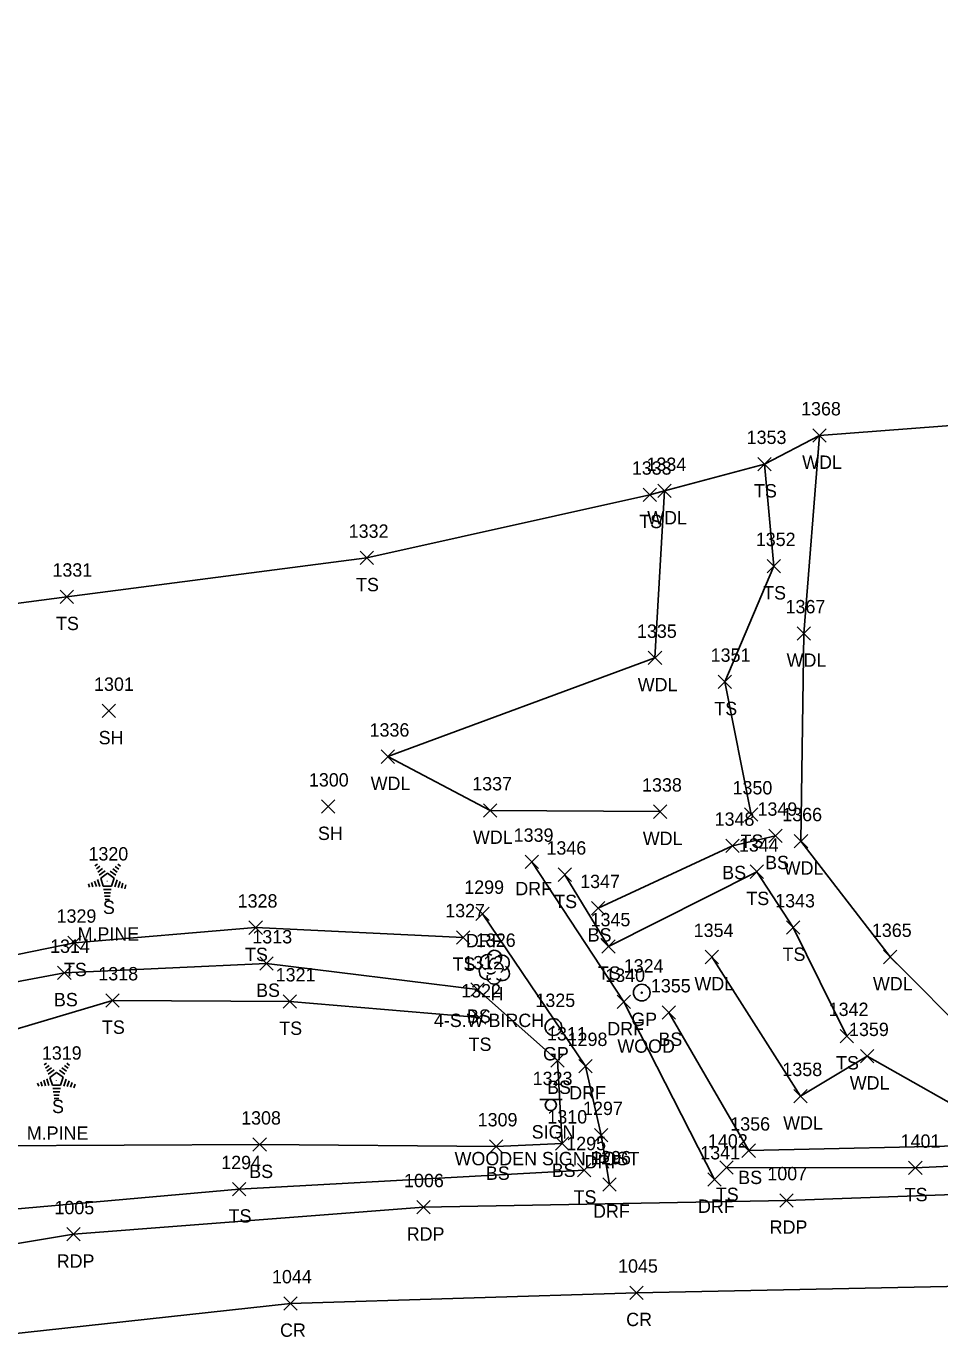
# Model space of a CAD drawing. Extents: x 1633660 to 1636532, y 388643 to 392631.
# Drawn here: x 1633769.3 to 1633906, y 388760.6 to 388957.6 of the extents above; entities that cross this region are included whole.
import ezdxf

# ---------------------------------------------------------------- set-up
doc = ezdxf.new("R2010")
doc.units = 0
for name, color, linetype in [('L_A', 7, 'Continuous'), ('L_C', 7, 'Continuous'), ('L_I', 7, 'Continuous'), ('L_TIC', 7, 'Continuous'), ('LAWA', 7, 'Continuous'), ('LELB', 7, 'Continuous'), ('LSOGP', 7, 'Continuous'), ('LTC', 7, 'Continuous'), ('LTD', 7, 'Continuous'), ('P_A', 7, 'Continuous'), ('P_I', 7, 'Continuous'), ('P_TIC', 7, 'Continuous'), ('PET', 7, 'Continuous'), ('PRC', 7, 'Continuous'), ('R_A', 7, 'Continuous'), ('R_C', 7, 'Continuous'), ('R_I', 7, 'Continuous'), ('R_TIC', 7, 'Continuous'), ('RDF', 7, 'Continuous'), ('RGP', 7, 'Continuous'), ('S_A', 7, 'Continuous'), ('S_C', 7, 'Continuous'), ('S_I', 7, 'Continuous'), ('SSGN', 7, 'Continuous')]:
    doc.layers.add(name, color=color, linetype=linetype)

msp = doc.modelspace()

# ---------------------------------------------------------------- linework, layer by layer
at = {"layer": 'L_TIC'}
for points in [[(1633886.99, 388895.34), (1633888.99, 388897.34)], [(1633888.99, 388895.34), (1633886.99, 388897.34)], [(1633878.79, 388891.06), (1633880.79, 388893.06)], [(1633880.79, 388891.06), (1633878.79, 388893.06)], [(1633861.62, 388886.47), (1633863.62, 388888.47)], [(1633863.62, 388886.47), (1633861.62, 388888.47)], [(1633863.8, 388887.03), (1633865.8, 388889.03)], [(1633865.8, 388887.03), (1633863.8, 388889.03)], [(1633819.24, 388877.02), (1633821.24, 388879.02)], [(1633821.24, 388877.02), (1633819.24, 388879.02)], [(1633880.16, 388875.79), (1633882.16, 388877.79)], [(1633882.16, 388875.79), (1633880.16, 388877.79)], [(1633774.34, 388871.21), (1633776.34, 388873.21)], [(1633776.34, 388871.21), (1633774.34, 388873.21)], [(1633884.66, 388865.72), (1633886.66, 388867.72)], [(1633886.66, 388865.72), (1633884.66, 388867.72)], [(1633862.38, 388862.05), (1633864.38, 388864.05)], [(1633864.38, 388862.05), (1633862.38, 388864.05)], [(1633872.85, 388858.47), (1633874.85, 388860.47)], [(1633874.85, 388858.47), (1633872.85, 388860.47)], [(1633780.65, 388854.12), (1633782.65, 388856.12)], [(1633782.65, 388854.12), (1633780.65, 388856.12)], [(1633822.41, 388847.27), (1633824.41, 388849.27)], [(1633824.41, 388847.27), (1633822.41, 388849.27)], [(1633813.45, 388839.8), (1633815.45, 388841.8)], [(1633815.45, 388839.8), (1633813.45, 388841.8)], [(1633837.72, 388839.22), (1633839.72, 388841.22)], [(1633839.72, 388839.22), (1633837.72, 388841.22)], [(1633863.15, 388839.04), (1633865.15, 388841.04)], [(1633865.15, 388839.04), (1633863.15, 388841.04)], [(1633876.77, 388838.62), (1633878.77, 388840.62)], [(1633878.77, 388838.62), (1633876.77, 388840.62)], [(1633880.42, 388835.43), (1633882.42, 388837.43)], [(1633882.42, 388835.43), (1633880.42, 388837.43)], [(1633874, 388833.93), (1633876, 388835.93)], [(1633876, 388833.93), (1633874, 388835.93)], [(1633884.23, 388834.61), (1633886.23, 388836.61)], [(1633886.23, 388834.61), (1633884.23, 388836.61)], [(1633848.89, 388829.61), (1633850.89, 388831.61)], [(1633850.89, 388829.61), (1633848.89, 388831.61)], [(1633877.64, 388830.06), (1633879.64, 388832.06)], [(1633879.64, 388830.06), (1633877.64, 388832.06)], [(1633853.87, 388824.6), (1633855.87, 388826.6)], [(1633855.87, 388824.6), (1633853.87, 388826.6)], [(1633802.62, 388821.68), (1633804.62, 388823.68)], [(1633804.62, 388821.68), (1633802.62, 388823.68)], [(1633883.07, 388821.71), (1633885.07, 388823.71)], [(1633885.07, 388821.71), (1633883.07, 388823.71)], [(1633775.53, 388819.42), (1633777.53, 388821.42)], [(1633777.53, 388819.42), (1633775.53, 388821.42)], [(1633833.68, 388820.23), (1633835.68, 388822.23)], [(1633835.68, 388820.23), (1633833.68, 388822.23)], [(1633855.43, 388818.88), (1633857.43, 388820.88)], [(1633857.43, 388818.88), (1633855.43, 388820.88)], [(1633870.87, 388817.29), (1633872.87, 388819.29)], [(1633872.87, 388817.29), (1633870.87, 388819.29)], [(1633897.58, 388817.29), (1633899.58, 388819.29)], [(1633899.58, 388817.29), (1633897.58, 388819.29)], [(1633804.25, 388816.32), (1633806.25, 388818.32)], [(1633806.25, 388816.32), (1633804.25, 388818.32)], [(1633773.99, 388814.91), (1633775.99, 388816.91)], [(1633775.99, 388814.91), (1633773.99, 388816.91)], [(1633835.81, 388812.44), (1633837.81, 388814.44)], [(1633837.81, 388812.44), (1633835.81, 388814.44)], [(1633781.21, 388810.79), (1633783.21, 388812.79)], [(1633783.21, 388810.79), (1633781.21, 388812.79)], [(1633807.74, 388810.63), (1633809.74, 388812.63)], [(1633809.74, 388810.63), (1633807.74, 388812.63)], [(1633836.08, 388808.23), (1633838.08, 388810.23)], [(1633838.08, 388808.23), (1633836.08, 388810.23)], [(1633864.46, 388808.99), (1633866.46, 388810.99)], [(1633866.46, 388808.99), (1633864.46, 388810.99)], [(1633891.07, 388805.46), (1633893.07, 388807.46)], [(1633893.07, 388805.46), (1633891.07, 388807.46)], [(1633847.79, 388801.8), (1633849.79, 388803.8)], [(1633849.79, 388801.8), (1633847.79, 388803.8)], [(1633894.12, 388802.46), (1633896.12, 388804.46)], [(1633896.12, 388802.46), (1633894.12, 388804.46)], [(1633884.15, 388796.47), (1633886.15, 388798.47)], [(1633886.15, 388796.47), (1633884.15, 388798.47)], [(1633803.22, 388789.21), (1633805.22, 388791.21)], [(1633805.22, 388789.21), (1633803.22, 388791.21)], [(1633838.63, 388788.94), (1633840.63, 388790.94)], [(1633840.63, 388788.94), (1633838.63, 388790.94)], [(1633848.49, 388789.37), (1633850.49, 388791.37)], [(1633850.49, 388789.37), (1633848.49, 388791.37)], [(1633876.4, 388788.31), (1633878.4, 388790.31)], [(1633878.4, 388788.31), (1633876.4, 388790.31)], [(1633873.08, 388785.77), (1633875.08, 388787.77)], [(1633875.08, 388785.77), (1633873.08, 388787.77)], [(1633901.34, 388785.74), (1633903.34, 388787.74)], [(1633903.34, 388785.74), (1633901.34, 388787.74)], [(1633851.79, 388785.38), (1633853.79, 388787.38)], [(1633853.79, 388785.38), (1633851.79, 388787.38)], [(1633800.16, 388782.54), (1633802.16, 388784.54)], [(1633802.16, 388782.54), (1633800.16, 388784.54)]]:
    msp.add_lwpolyline(points, dxfattribs=at)
at = {"layer": 'LAWA'}
for points in [[(1633871.87, 388818.29), (1633885.15, 388797.47), (1633895.12, 388803.46), (1633913.82, 388792.88), (1633930.93, 388800.92), (1633911.2, 388805.65), (1633898.58, 388818.29), (1633885.23, 388835.61), (1633885.66, 388866.72), (1633887.99, 388896.34)], [(1633864.8, 388888.03), (1633863.38, 388863.05), (1633823.41, 388848.27), (1633838.72, 388840.22), (1633864.15, 388840.04)]]:
    msp.add_lwpolyline(points, dxfattribs=at)
at = {"layer": 'LELB'}
for points in [[(1633877.77, 388839.62), (1633873.85, 388859.47), (1633881.16, 388876.79), (1633879.79, 388892.06)], [(1633775.34, 388872.21), (1633820.24, 388878.02), (1633862.62, 388887.47)], [(1633690.59, 388853.77), (1633701.55, 388823.73), (1633717.77, 388794.21), (1633733.79, 388778.78), (1633764.59, 388780.31), (1633801.16, 388783.54), (1633852.79, 388786.38)], [(1633865.46, 388809.99), (1633877.4, 388789.31), (1633913.51, 388790.13), (1633934.95, 388796.07), (1633973.78, 388798.8), (1634008.4, 388803.18), (1634057.79, 388813.56), (1634087.95, 388824.89), (1634134.34, 388843.13)], [(1634140.78, 388840.91), (1634131.75, 388832.34), (1634088.08, 388818.52), (1634045.58, 388805.1), (1633995.02, 388794.98), (1633949.56, 388789), (1633902.34, 388786.74), (1633874.08, 388786.77)], [(1633854.87, 388825.6), (1633875, 388834.93), (1633881.42, 388836.43)], [(1633892.07, 388806.46), (1633884.07, 388822.71), (1633878.64, 388831.06), (1633856.43, 388819.88), (1633849.89, 388830.61)], [(1633834.68, 388821.23), (1633803.62, 388822.68), (1633776.53, 388820.42), (1633736.77, 388812.27)], [(1633732.52, 388802.79), (1633737.38, 388786.25), (1633763.6, 388790.01), (1633804.22, 388790.21), (1633839.63, 388789.94), (1633849.49, 388790.37), (1633848.79, 388802.8), (1633836.81, 388813.44), (1633805.25, 388817.32), (1633774.99, 388815.91), (1633736.68, 388808.76)], [(1633736.45, 388802.86), (1633755.65, 388803.9), (1633782.21, 388811.79), (1633808.74, 388811.63), (1633837.08, 388809.23)]]:
    msp.add_lwpolyline(points, dxfattribs=at)
at = {"layer": 'LSOGP'}
msp.add_lwpolyline([(1633910.94, 388898.06), (1633887.99, 388896.34), (1633879.79, 388892.06), (1633864.8, 388888.03), (1633862.62, 388887.47), (1633820.24, 388878.02), (1633775.34, 388872.21), (1633743.09, 388867.97), (1633701.66, 388850.69), (1633690.59, 388853.77), (1633685.99, 388855.24), (1633676.03, 388842.96), (1633671.44, 388843.54), (1633662.45, 388842.61), (1633668.86, 388816.92), (1633674.86, 388781.37), (1633677.6, 388769.11), (1633680.44, 388762.93), (1633681.12, 388754.49)], dxfattribs=at)
at = {"layer": 'LTC'}
for p, q in [((1633779.57, 388831.94), (1633779.93, 388832.2)), ((1633779.78, 388831.48), (1633780.31, 388831.86)), ((1633779.99, 388831.01), (1633780.7, 388831.52)), ((1633780.2, 388830.54), (1633781.08, 388831.18)), ((1633781.86, 388831.14), (1633782.67, 388830.55)), ((1633782.23, 388831.48), (1633782.91, 388830.99)), ((1633782.6, 388831.83), (1633783.15, 388831.43)), ((1633782.97, 388832.18), (1633783.39, 388831.88)), ((1633778.61, 388829.22), (1633778.76, 388828.75)), ((1633779.06, 388829.44), (1633779.27, 388828.78)), ((1633779.52, 388829.65), (1633779.79, 388828.82)), ((1633779.97, 388829.87), (1633780.3, 388828.85)), ((1633780.43, 388830.09), (1633781.44, 388830.82)), ((1633780.43, 388830.09), (1633780.81, 388828.9)), ((1633781.44, 388830.82), (1633782.44, 388830.1)), ((1633782.44, 388830.1), (1633782.04, 388828.9)), ((1633782.87, 388829.83), (1633782.54, 388828.79)), ((1633783.32, 388829.58), (1633783.03, 388828.69)), ((1633783.76, 388829.33), (1633783.53, 388828.6)), ((1633784.21, 388829.08), (1633784.02, 388828.5)), ((1633782.04, 388828.9), (1633780.81, 388828.9)), ((1633782.01, 388828.4), (1633780.86, 388828.4)), ((1633781.92, 388827.9), (1633780.93, 388827.9)), ((1633781.84, 388827.4), (1633781.01, 388827.4)), ((1633781.76, 388826.9), (1633781.08, 388826.9)), ((1633771.96, 388802.14), (1633772.32, 388802.39)), ((1633772.17, 388801.67), (1633772.7, 388802.05)), ((1633772.38, 388801.2), (1633773.08, 388801.72)), ((1633772.59, 388800.74), (1633773.47, 388801.38)), ((1633774.62, 388801.68), (1633775.3, 388801.19)), ((1633774.99, 388802.03), (1633775.54, 388801.63)), ((1633775.36, 388802.38), (1633775.78, 388802.07)), ((1633770.99, 388799.41), (1633771.15, 388798.95)), ((1633771.45, 388799.63), (1633771.66, 388798.98)), ((1633771.91, 388799.85), (1633772.18, 388799.01)), ((1633772.36, 388800.06), (1633772.69, 388799.04)), ((1633772.82, 388800.28), (1633773.83, 388801.02)), ((1633772.82, 388800.28), (1633773.2, 388799.09)), ((1633773.83, 388801.02), (1633774.82, 388800.29)), ((1633774.25, 388801.33), (1633775.06, 388800.74)), ((1633774.82, 388800.29), (1633774.43, 388799.09)), ((1633775.26, 388800.02), (1633774.92, 388798.98)), ((1633775.71, 388799.77), (1633775.42, 388798.89)), ((1633776.15, 388799.52), (1633775.91, 388798.79)), ((1633774.43, 388799.09), (1633773.2, 388799.09)), ((1633774.39, 388798.59), (1633773.25, 388798.59)), ((1633774.31, 388798.09), (1633773.32, 388798.09)), ((1633774.23, 388797.59), (1633773.4, 388797.59)), ((1633776.59, 388799.27), (1633776.41, 388798.7)), ((1633774.14, 388797.09), (1633773.47, 388797.09))]:
    msp.add_line(p, q, dxfattribs=at)
at = {"layer": 'LTD'}
msp.add_line((1633839.32, 388816.81), (1633839.32, 388816.81), dxfattribs=at)
msp.add_line((1633839.32, 388816.81), (1633839.32, 388816.81), dxfattribs=at)
msp.add_arc((1633839.37, 388818.25), 1.05, 335.5272, 180.9563, dxfattribs=at)
for centre, major_axis, ratio, start_param, end_param in [((1633838.24, 388816.1), (0.58, -1.04), 0.959034, 3.141593, 6.283185), ((1633838.53, 388817.48), (1.21, -0.51), 0.895232, 1.570796, 4.712389), ((1633839.11, 388817.27), (-0.208, -0.792), 0.645439, 3.141593, 6.283185), ((1633839.82, 388816.64), (-0.5, 0.667), 0.989748, 3.141593, 6.283185), ((1633840.36, 388817.4), (-1.14, -0.48), 0.949671, 1.570796, 4.712389), ((1633839.32, 388815.31), (0.26, 1.06), 0.942809, 1.570796, 4.712389), ((1633838.87, 388816.06), (-0.625, -0.083), 0.423636, 0, 3.141593), ((1633840.32, 388815.98), (-1.09, 0.79), 0.841452, 1.570796, 4.712389)]:
    msp.add_ellipse(centre, major_axis=major_axis, ratio=ratio, start_param=start_param, end_param=end_param, dxfattribs=at)
at = {"layer": 'P_TIC'}
for points in [[(1633827.74, 388779.84), (1633829.74, 388781.84)], [(1633829.74, 388779.84), (1633827.74, 388781.84)], [(1633882.05, 388780.87), (1633884.05, 388782.87)], [(1633884.05, 388780.87), (1633882.05, 388782.87)], [(1633775.36, 388775.79), (1633777.36, 388777.79)], [(1633777.36, 388775.79), (1633775.36, 388777.79)], [(1633859.63, 388767.05), (1633861.63, 388769.05)], [(1633861.63, 388767.05), (1633859.63, 388769.05)], [(1633807.84, 388765.45), (1633809.84, 388767.45)], [(1633809.84, 388765.45), (1633807.84, 388767.45)]]:
    msp.add_lwpolyline(points, dxfattribs=at)
at = {"layer": 'PET'}
msp.add_lwpolyline([(1633681.12, 388754.49), (1633725.19, 388768.3), (1633776.36, 388776.79), (1633828.74, 388780.84), (1633883.05, 388781.87), (1633940.05, 388783.92), (1633980.78, 388788.35), (1634030.66, 388797.38), (1634082.16, 388811.29), (1634131.93, 388828.18), (1634182.59, 388846.73), (1634235.61, 388867.86)], dxfattribs=at)
at = {"layer": 'PRC'}
msp.add_lwpolyline([(1633685.21, 388740.89), (1633722.47, 388753.09), (1633765.95, 388761.74), (1633808.84, 388766.45), (1633860.63, 388768.05), (1633911.93, 388769.08), (1633965.45, 388772.58), (1634019.68, 388781.06), (1634071.37, 388793.87), (1634111.14, 388806.36), (1634160.92, 388824.06), (1634207.93, 388842.02), (1634253.71, 388860.36), (1634302.74, 388880.25), (1634347.86, 388899.14), (1634390.05, 388916.89), (1634425.6, 388933.8), (1634443.27, 388943.77), (1634464.46, 388957.57)], dxfattribs=at)
at = {"layer": 'R_TIC'}
for points in [[(1633843.94, 388831.53), (1633845.94, 388833.53)], [(1633845.94, 388831.53), (1633843.94, 388833.53)], [(1633836.55, 388823.74), (1633838.55, 388825.74)], [(1633838.55, 388823.74), (1633836.55, 388825.74)], [(1633857.71, 388810.56), (1633859.71, 388812.56)], [(1633859.71, 388810.56), (1633857.71, 388812.56)], [(1633852, 388800.97), (1633854, 388802.97)], [(1633854, 388800.97), (1633852, 388802.97)], [(1633854.31, 388790.64), (1633856.31, 388792.64)], [(1633856.31, 388790.64), (1633854.31, 388792.64)], [(1633871.28, 388784), (1633873.28, 388786)], [(1633873.28, 388784), (1633871.28, 388786)], [(1633855.58, 388783.26), (1633857.58, 388785.26)], [(1633857.58, 388783.26), (1633855.58, 388785.26)]]:
    msp.add_lwpolyline(points, dxfattribs=at)
at = {"layer": 'RDF'}
for points in [[(1633844.94, 388832.53), (1633858.71, 388811.56), (1633872.28, 388785)], [(1633856.58, 388784.26), (1633855.31, 388791.64), (1633853, 388801.97), (1633837.55, 388824.74)]]:
    msp.add_lwpolyline(points, dxfattribs=at)
at = {"layer": 'RGP'}
for p, q in [((1633861.4, 388812.96), (1633861.4, 388812.96)), ((1633848.18, 388807.81), (1633848.18, 388807.81))]:
    msp.add_line(p, q, dxfattribs=at)
for centre, radius in [((1633861.4, 388812.96), 1.25), ((1633861.4, 388812.96), 0.0833), ((1633848.18, 388807.81), 1.25), ((1633848.18, 388807.81), 0.0833)]:
    msp.add_circle(centre, radius, dxfattribs=at)
at = {"layer": 'SSGN'}
for p, q in [((1633846.15, 388796.98), (1633849.48, 388796.98)), ((1633847.79, 388796.14), (1633847.79, 388796.14))]:
    msp.add_line(p, q, dxfattribs=at)
msp.add_circle((1633847.79, 388796.14), 0.833, dxfattribs=at)

# ---------------------------------------------------------------- texts
at = {"layer": 'L_A'}
for s, p in [('WDL', (1633885.41, 388891.34)), ('TS', (1633878.2, 388887.06)), ('TS', (1633861.03, 388882.47)), ('WDL', (1633862.22, 388883.03)), ('TS', (1633818.65, 388873.02)), ('TS', (1633879.57, 388871.79)), ('TS', (1633773.75, 388867.21)), ('WDL', (1633883.08, 388861.72)), ('WDL', (1633860.8, 388858.05)), ('TS', (1633872.26, 388854.47)), ('SH', (1633780.13, 388850.12)), ('WDL', (1633820.83, 388843.27)), ('SH', (1633812.94, 388835.8)), ('WDL', (1633836.14, 388835.22)), ('WDL', (1633861.56, 388835.04)), ('TS', (1633876.18, 388834.62)), ('BS', (1633879.86, 388831.43)), ('BS', (1633873.44, 388829.93)), ('WDL', (1633882.64, 388830.61)), ('TS', (1633848.3, 388825.61)), ('TS', (1633877.05, 388826.06)), ('S', (1633780.76, 388824.73)), ('BS', (1633853.31, 388820.6)), ('TS', (1633802.03, 388817.68)), ('TS', (1633882.47, 388817.71)), ('TS', (1633774.94, 388815.42)), ('TS', (1633833.09, 388816.23)), ('TS', (1633854.84, 388814.88)), ('WDL', (1633869.29, 388813.29)), ('WDL', (1633896, 388813.29)), ('BS', (1633803.69, 388812.32)), ('H', (1633838.76, 388811.81)), ('BS', (1633773.43, 388810.91)), ('BS', (1633835.25, 388808.44)), ('TS', (1633780.62, 388806.79)), ('TS', (1633807.15, 388806.63)), ('TS', (1633835.49, 388804.23)), ('BS', (1633863.9, 388804.99)), ('TS', (1633890.48, 388801.46)), ('BS', (1633847.23, 388797.8)), ('WDL', (1633892.53, 388798.46)), ('S', (1633773.15, 388794.93)), ('WDL', (1633882.56, 388792.47)), ('BS', (1633802.66, 388785.21)), ('BS', (1633838.07, 388784.94)), ('BS', (1633847.93, 388785.37)), ('BS', (1633875.84, 388784.31)), ('TS', (1633872.49, 388781.77)), ('TS', (1633900.75, 388781.74)), ('TS', (1633851.2, 388781.38)), ('TS', (1633799.57, 388778.54))]:
    msp.add_text(s, height=2, dxfattribs=at).set_placement(p)
at = {"layer": 'L_C'}
for s, p in [('M.PINE', (1633776.98, 388820.73)), ('4-S.W BIRCH', (1633830.3, 388807.81)), ('M.PINE', (1633769.37, 388790.93))]:
    msp.add_text(s, height=2, dxfattribs=at).set_placement(p)
at = {"layer": 'L_I'}
for s, p in [('1368', (1633885.25, 388899.34)), ('1353', (1633877.1, 388895.06)), ('1333', (1633859.92, 388890.47)), ('1334', (1633862.11, 388891.03)), ('1332', (1633817.55, 388881.02)), ('1352', (1633878.47, 388879.79)), ('1331', (1633773.21, 388875.21)), ('1367', (1633882.92, 388869.72)), ('1335', (1633860.69, 388866.05)), ('1351', (1633871.72, 388862.47)), ('1301', (1633779.44, 388858.12)), ('1336', (1633820.67, 388851.27)), ('1300', (1633811.59, 388843.8)), ('1337', (1633836.03, 388843.22)), ('1338', (1633861.45, 388843.04)), ('1350', (1633874.99, 388842.62)), ('1349', (1633878.72, 388839.43)), ('1348', (1633872.31, 388837.93)), ('1366', (1633882.43, 388838.61)), ('1346', (1633847.14, 388833.61)), ('1344', (1633875.94, 388834.06)), ('1320', (1633778.6, 388832.73)), ('1347', (1633852.18, 388828.6)), ('1328', (1633800.93, 388825.68)), ('1343', (1633881.37, 388825.71)), ('1329', (1633773.83, 388823.42)), ('1327', (1633831.99, 388824.23)), ('1345', (1633853.74, 388822.88)), ('1354', (1633869.18, 388821.29)), ('1365', (1633895.84, 388821.29)), ('1313', (1633803.13, 388820.32)), ('1326', (1633836.58, 388819.81)), ('1314', (1633772.86, 388818.91)), ('1312', (1633834.69, 388816.44)), ('1318', (1633780.08, 388814.79)), ('1321', (1633806.62, 388814.63)), ('1322', (1633834.38, 388812.23)), ('1355', (1633862.77, 388812.99)), ('1342', (1633889.38, 388809.46)), ('1311', (1633847.23, 388805.8)), ('1359', (1633892.42, 388806.46)), ('1319', (1633771.63, 388802.93)), ('1358', (1633882.45, 388800.47)), ('1308', (1633801.45, 388793.21)), ('1309', (1633836.85, 388792.94)), ('1310', (1633847.28, 388793.37)), ('1356', (1633874.65, 388792.31)), ('1402', (1633871.31, 388789.77)), ('1401', (1633900.14, 388789.74)), ('1295', (1633850.1, 388789.38)), ('1294', (1633798.47, 388786.54))]:
    msp.add_text(s, height=2, dxfattribs=at).set_placement(p)
at = {"layer": 'LTC'}
for p in [(1633781.32, 388829.84), (1633773.71, 388800.03)]:
    msp.add_text('.', height=1.04, rotation=270, dxfattribs=at).set_placement(p)
at = {"layer": 'P_A'}
for s, p in [('RDP', (1633826.23, 388775.84)), ('RDP', (1633880.54, 388776.87)), ('RDP', (1633773.85, 388771.79)), ('CR', (1633859.07, 388763.05)), ('CR', (1633807.27, 388761.45))]:
    msp.add_text(s, height=2, dxfattribs=at).set_placement(p)
at = {"layer": 'P_I'}
for s, p in [('1006', (1633825.83, 388783.84)), ('1007', (1633880.2, 388784.87)), ('1005', (1633773.51, 388779.79)), ('1045', (1633857.86, 388771.05)), ('1044', (1633806.07, 388769.45))]:
    msp.add_text(s, height=2, dxfattribs=at).set_placement(p)
at = {"layer": 'R_A'}
for s, p in [('DRF', (1633842.48, 388827.53)), ('DRF', (1633835.08, 388819.74)), ('GP', (1633859.83, 388807.96)), ('DRF', (1633856.25, 388806.56)), ('GP', (1633846.62, 388802.81)), ('DRF', (1633850.54, 388796.97)), ('DRF', (1633852.85, 388786.64)), ('DRF', (1633869.82, 388780)), ('DRF', (1633854.11, 388779.26))]:
    msp.add_text(s, height=2, dxfattribs=at).set_placement(p)
at = {"layer": 'R_C'}
msp.add_text('WOOD', height=2, dxfattribs=at).set_placement((1633857.75, 388803.96))
at = {"layer": 'R_I'}
for s, p in [('1339', (1633842.24, 388835.53)), ('1299', (1633834.84, 388827.74)), ('1324', (1633858.71, 388815.96)), ('1340', (1633855.94, 388814.56)), ('1325', (1633845.49, 388810.81)), ('1298', (1633850.31, 388804.97)), ('1297', (1633852.62, 388794.64)), ('1341', (1633870.16, 388788)), ('1296', (1633853.83, 388787.26))]:
    msp.add_text(s, height=2, dxfattribs=at).set_placement(p)
at = {"layer": 'S_A'}
msp.add_text('SIGN', height=2, dxfattribs=at).set_placement((1633844.93, 388791.12))
at = {"layer": 'S_C'}
msp.add_text('WOODEN SIGN POST', height=2, dxfattribs=at).set_placement((1633833.39, 388787.12))
at = {"layer": 'S_I'}
msp.add_text('1323', height=2, dxfattribs=at).set_placement((1633845.08, 388799.12))

doc.saveas('drawing.dxf')
